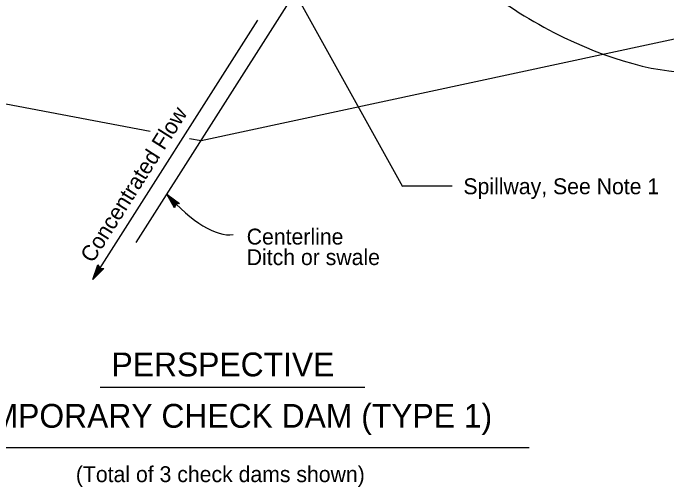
# Model space of a CAD drawing. Extents: x 6707415 to 6708768, y 1869893 to 1870831.
# Drawn here: x 6707644.1 to 6707891.3, y 1870013.7 to 1870192.8 of the extents above; entities that cross this region are included whole.
import ezdxf

# ---------------------------------------------------------------- set-up
doc = ezdxf.new("R2010")
doc.units = 0
for name, color, linetype in [('56 Stg 3 Anno', 7, 'Continuous'), ('57 Undefined', 7, 'Continuous'), ('60 Nongeo Data', 7, 'Continuous')]:
    doc.layers.add(name, color=color, linetype=linetype)

msp = doc.modelspace()

# ---------------------------------------------------------------- linework, layer by layer
at = {"layer": '56 Stg 3 Anno'}
for p, q in [((6707737.98, 1870223.41), (6707791.39, 1870127.24)), ((6707674.27, 1870092.09), (6707736.61, 1870190.07)), ((6707810.13, 1870127.33), (6707791.57, 1870127.33)), ((6707705.17, 1870119.15), (6707702.29, 1870124.3)), ((6707702.29, 1870124.3), (6707702.29, 1870124.3)), ((6707702.29, 1870124.3), (6707707.08, 1870120.86)), ((6707705.28, 1870119.53), (6707703.17, 1870123.31)), ((6707703.18, 1870123.31), (6707706.67, 1870120.8)), ((6707705.39, 1870119.93), (6707704.05, 1870122.32)), ((6707704.05, 1870122.32), (6707706.31, 1870120.7)), ((6707705.53, 1870120.28), (6707704.94, 1870121.33)), ((6707704.94, 1870121.33), (6707705.9, 1870120.64)), ((6707707.08, 1870120.86), (6707705.61, 1870120.58)), ((6707707.08, 1870120.86), (6707707.08, 1870120.86)), ((6707705.61, 1870120.58), (6707705.17, 1870119.15)), ((6707705.17, 1870119.15), (6707705.17, 1870119.15)), ((6707674.27, 1870092.09), (6707676.2, 1870097.66)), ((6707678.38, 1870096.31), (6707674.27, 1870092.09)), ((6707674.96, 1870093.22), (6707676.38, 1870097.29)), ((6707677.98, 1870096.32), (6707674.96, 1870093.21)), ((6707675.66, 1870094.34), (6707676.57, 1870096.97)), ((6707677.57, 1870096.31), (6707675.66, 1870094.34)), ((6707676.2, 1870097.66), (6707676.2, 1870097.66)), ((6707676.2, 1870097.66), (6707676.89, 1870096.33)), ((6707676.36, 1870095.47), (6707676.75, 1870096.59)), ((6707677.2, 1870096.34), (6707676.36, 1870095.47)), ((6707676.89, 1870096.33), (6707678.38, 1870096.31)), ((6707678.38, 1870096.31), (6707678.38, 1870096.31)), ((6707674.27, 1870092.09), (6707674.27, 1870092.09))]:
    msp.add_line(p, q, dxfattribs=at)
for centre, major_axis, ratio, start_param, end_param in [((6707855.02, 1870222.1), (68.84, -42.22), 0.434429, 4.031868, 5.732815), ((6707701.11, 1870170.81), (-29.01, 60.95), 0.360833, 2.25187, 3.024453)]:
    msp.add_ellipse(centre, major_axis=major_axis, ratio=ratio, start_param=start_param, end_param=end_param, dxfattribs=at)
at = {"layer": '57 Undefined'}
for p, q in [((6707677.02, 1870051.42), (6707777.06, 1870051.42)), ((6707618.44, 1870028.6), (6707839.24, 1870028.6))]:
    msp.add_line(p, q, dxfattribs=at)
at = {"layer": '60 Nongeo Data'}
msp.add_line((6707690.72, 1870106.12), (6707748.46, 1870196.87), dxfattribs=at)
for points in [[(6707486.86, 1870187.72), (6707695.92, 1870148.21)], [(6707715.19, 1870144.57), (6707919.37, 1870188.45)], [(6707710.87, 1870145.39), (6707715.18, 1870144.57)]]:
    msp.add_lwpolyline(points, dxfattribs=at)

# ---------------------------------------------------------------- texts
at = {"layer": '57 Undefined'}
msp.add_text('Concentrated Flow', height=6, rotation=57.6809, dxfattribs=at).set_placement((6707674.25, 1870098.02))
for s, height, p in [('Spillway, See Note 1', 6, (6707814.39, 1870124.33)), ('Centerline', 6, (6707732.46, 1870105.32)), ('Ditch or swale', 6, (6707732.46, 1870097.55)), ('PERSPECTIVE', 9, (6707681.35, 1870055.5)), ('TEMPORARY CHECK DAM (TYPE 1)', 9, (6707620.63, 1870036.08)), ('(Total of 3 check dams shown)', 6, (6707667.85, 1870015.53))]:
    msp.add_text(s, height=height, dxfattribs=at).set_placement(p)

doc.saveas('drawing.dxf')
